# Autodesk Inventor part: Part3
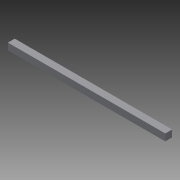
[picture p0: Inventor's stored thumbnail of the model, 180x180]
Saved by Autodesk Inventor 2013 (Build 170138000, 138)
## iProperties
Created: 2013-06
Part Number: Part3
Material: Generic
Document SubType Name: Modeling
Designer: jpfenske
Mass: 1272.05 g
Surface Area: 1364.51 cm^2
Volume: 1272.05 cm^3
Density: 1 g/cm^3
Author: jpfenske
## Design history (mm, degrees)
sketch "Sketch1"
  geometry: L1 (-414.892, 325.462)-(461.408, 325.462); L2 (461.408, 325.462)-(461.408, 287.362); L3 (461.408, 287.362)-(-414.892, 287.362); L4 (-414.892, 287.362)-(-414.892, 325.462); 1 further point
  constraints: 8 end point, 2 parallel, 1 horizontal, 1 perpendicular
  dimensions: "d0" = 876.3 distance of L1.start L1.end; "d1" = 38.1 distance of L1.end L2.end
extrude "Extrusion1" new body sketch "Sketch1" distance "d2" = 38.1; taper "d3" = 0 deg
body "Solid1"
